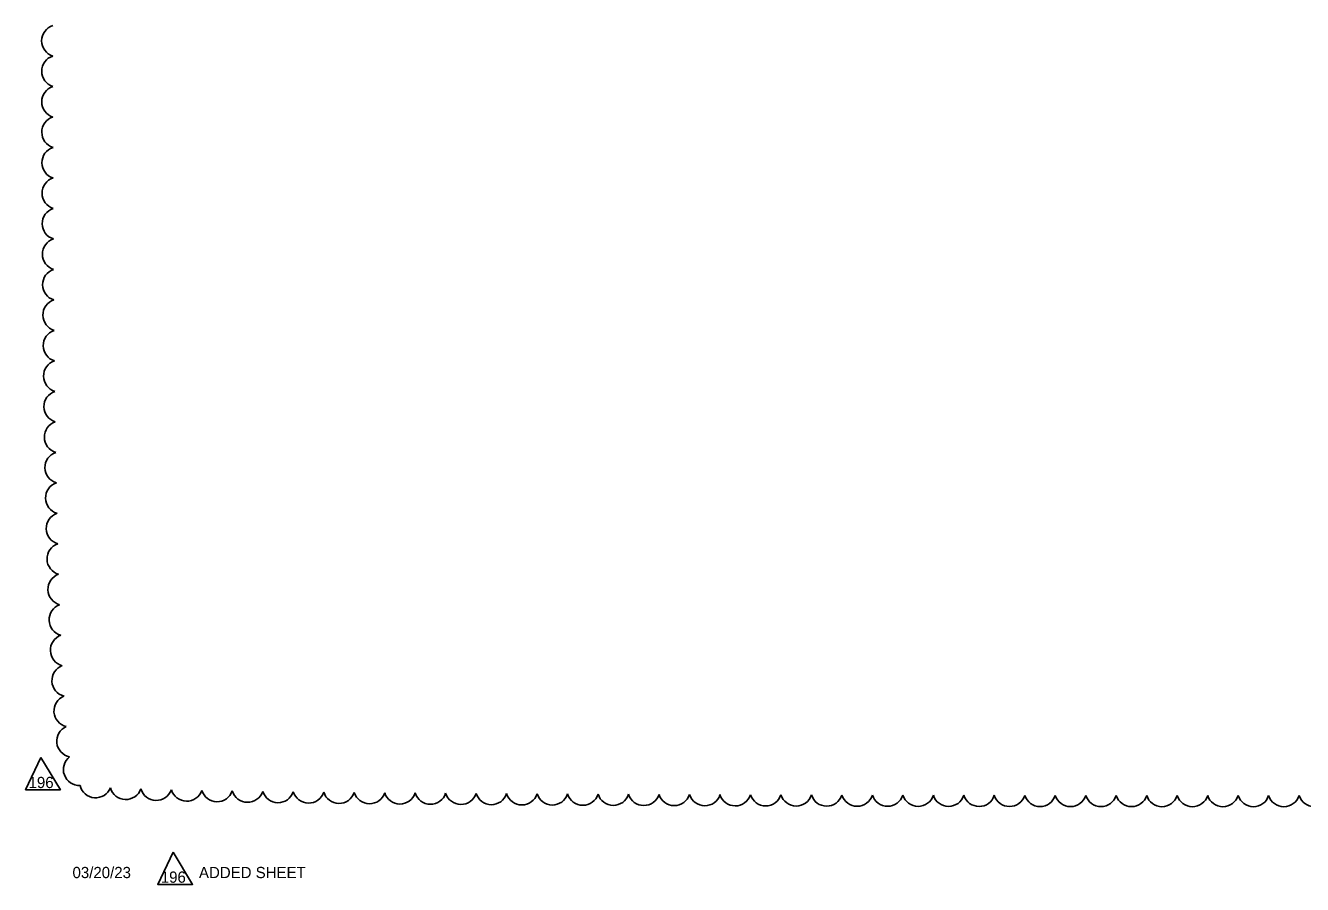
# Model space of a CAD drawing. Extents: x -811 to -790, y -2284 to -2178.
# Drawn here: x -811.08 to -803.16, y -2270.7 to -2265.38 of the extents above; entities that cross this region are included whole.
import ezdxf

# ---------------------------------------------------------------- set-up
doc = ezdxf.new("R2010")
doc.units = 0
doc.layers.add('ScratchEle_dp', color=7, linetype='Continuous')

msp = doc.modelspace()

# ---------------------------------------------------------------- linework, layer by layer
at = {"layer": 'ScratchEle_dp'}
for points in [[(-810.9836, -2269.9151), (-811.0784, -2270.1158), (-810.8622, -2270.1158)], [(-810.1638, -2270.5019), (-810.2586, -2270.7026), (-810.0424, -2270.7026)]]:
    msp.add_lwpolyline(points, close=True, dxfattribs=at)
for centre, start, end in [((-810.8794, -2265.4725), 107.52584, 252.52584), ((-810.8792, -2265.6615), 107.56719, 252.56719), ((-810.8789, -2265.8505), 107.61129, 252.61129), ((-810.8785, -2266.0394), 107.65843, 252.65843), ((-810.8779, -2266.2284), 107.709, 252.709), ((-810.8771, -2266.4174), 107.76343, 252.76343), ((-810.8761, -2266.6063), 107.82224, 252.82224), ((-810.8749, -2266.7953), 107.88605, 252.88605), ((-810.8736, -2266.9843), 107.95561, 252.95561), ((-810.8719, -2267.1732), 108.03183, 253.03183), ((-810.87, -2267.3622), 108.11586, 253.11586), ((-810.8679, -2267.5511), 108.20912, 253.20912), ((-810.8653, -2267.74), 108.31345, 253.31345), ((-810.8625, -2267.929), 108.43121, 253.43121), ((-810.8592, -2268.1179), 108.56556, 253.56556), ((-810.8554, -2268.3067), 108.72081, 253.72081), ((-810.8511, -2268.4956), 108.903, 253.903), ((-810.8461, -2268.6844), 109.12096, 254.12096), ((-810.8403, -2268.8732), 109.38818, 254.38818), ((-810.8335, -2269.0619), 109.72657, 254.72657), ((-810.8255, -2269.2505), 110.17469, 255.17469), ((-810.8156, -2269.4389), 110.80877, 255.80877), ((-810.8031, -2269.6269), 111.80931, 256.80931), ((-810.7858, -2269.8141), 113.77584, 258.77584), ((-810.7447, -2269.9899), 127.48462, 272.48462), ((-810.644, -2270.0663), 193.17348, 338.17348), ((-810.4565, -2270.0769), 195.39639, 340.39639), ((-810.2679, -2270.0828), 195.97806, 340.97806), ((-810.0791, -2270.0874), 196.28744, 341.28744), ((-809.8902, -2270.091), 196.48754, 341.48754), ((-809.7013, -2270.0941), 196.63065, 341.63065), ((-809.5124, -2270.0968), 196.73959, 341.73959), ((-809.3235, -2270.0992), 196.8261, 341.8261), ((-809.1345, -2270.1013), 196.89697, 341.89697), ((-808.9455, -2270.1032), 196.95641, 341.95641), ((-808.7566, -2270.1049), 197.0072, 342.0072), ((-808.5676, -2270.1064), 197.05125, 342.05125), ((-808.3786, -2270.1078), 197.08993, 342.08993), ((-808.1897, -2270.1091), 197.12425, 342.12425), ((-808.0007, -2270.1103), 197.15498, 342.15498), ((-807.8117, -2270.1114), 197.18269, 342.18269), ((-807.6227, -2270.1124), 197.20786, 342.20786), ((-807.4337, -2270.1134), 197.23085, 342.23085), ((-807.2447, -2270.1142), 197.25195, 342.25195), ((-807.0557, -2270.115), 197.27142, 342.27142), ((-806.8667, -2270.1157), 197.28945, 342.28945), ((-806.6778, -2270.1164), 197.30621, 342.30621), ((-806.4888, -2270.117), 197.32184, 342.32184), ((-806.2998, -2270.1176), 197.33647, 342.33647), ((-806.1108, -2270.1181), 197.3502, 342.3502), ((-805.9218, -2270.1186), 197.36311, 342.36311), ((-805.7328, -2270.119), 197.37529, 342.37529), ((-805.5438, -2270.1194), 197.3868, 342.3868), ((-805.3548, -2270.1197), 197.3977, 342.3977), ((-805.1658, -2270.1201), 197.40804, 342.40804), ((-804.9768, -2270.1203), 197.41787, 342.41787), ((-804.7878, -2270.1206), 197.42723, 342.42723), ((-804.5988, -2270.1208), 197.43616, 342.43616), ((-804.4098, -2270.121), 197.44468, 342.44468), ((-804.2208, -2270.1212), 197.45283, 342.45283), ((-804.0318, -2270.1213), 197.46064, 342.46064), ((-803.8428, -2270.1214), 197.46812, 342.46812), ((-803.6538, -2270.1215), 197.4753, 342.4753), ((-803.4648, -2270.1216), 197.4822, 342.4822), ((-803.2759, -2270.1217), 197.48884, 342.48884), ((-803.0869, -2270.1217), 197.49523, 342.49523)]:
    msp.add_arc(centre, 0.0991, start, end, dxfattribs=at)

# ---------------------------------------------------------------- texts
for s, p in [('196', (-811.0596, -2270.1051)), ('03/20/23', (-810.7871, -2270.6633)), ('ADDED SHEET', (-810.003, -2270.6633)), ('196', (-810.2398, -2270.6919))]:
    msp.add_text(s, height=0.0696, dxfattribs=at).set_placement(p)

doc.saveas('drawing.dxf')
